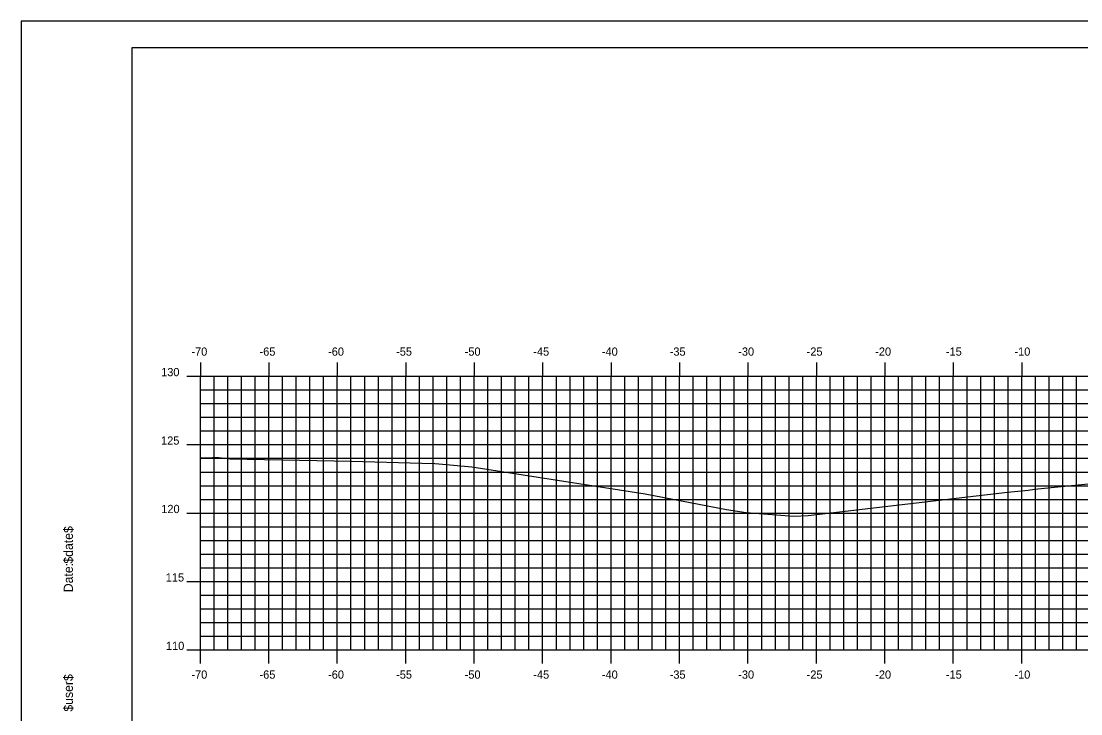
# Model space of a CAD drawing. Extents: x 852182 to 852354, y 365624 to 365734.
# Drawn here: x 852181.9 to 852259.3, y 365683.4 to 365734 of the extents above; entities that cross this region are included whole.
import ezdxf

# ---------------------------------------------------------------- set-up
doc = ezdxf.new("R2010")
doc.units = 0
for name, color, linetype in [('BORDER', 7, 'Continuous'), ('H_V ANNOTATION', 7, 'Continuous'), ('M_Roadway_Centerline', 7, 'Continuous'), ('MAJOR', 7, 'Continuous'), ('MINOR', 7, 'Continuous'), ('PLOT BOUNDARY', 7, 'Continuous'), ('S_Roadway_Centerline', 7, 'Continuous')]:
    doc.layers.add(name, color=color, linetype=linetype)

msp = doc.modelspace()

# ---------------------------------------------------------------- linework, layer by layer
at = {"layer": 'BORDER'}
msp.add_lwpolyline([(852190.035, 365627.027), (852350.035, 365627.027), (852350.035, 365732.027), (852190.035, 365732.027)], close=True, dxfattribs=at)
at = {"layer": 'MAJOR'}
for p, q in [((852195.035, 365709.029), (852195.035, 365708.027)), ((852200.035, 365709.029), (852200.035, 365708.027)), ((852205.035, 365709.029), (852205.035, 365708.027)), ((852210.035, 365709.029), (852210.035, 365708.027)), ((852215.035, 365709.029), (852215.035, 365708.027)), ((852220.035, 365709.029), (852220.035, 365708.027)), ((852225.035, 365709.029), (852225.035, 365708.027)), ((852230.035, 365709.029), (852230.035, 365708.027)), ((852235.035, 365709.029), (852235.035, 365708.027)), ((852240.035, 365709.029), (852240.035, 365708.027)), ((852245.035, 365709.029), (852245.035, 365708.027)), ((852250.035, 365709.029), (852250.035, 365708.027)), ((852255.035, 365709.029), (852255.035, 365708.027)), ((852194.033, 365708.027), (852195.035, 365708.027)), ((852195.035, 365708.027), (852335.035, 365708.027)), ((852195.035, 365688.027), (852195.035, 365708.027)), ((852195.035, 365688.027), (852195.035, 365708.027)), ((852195.035, 365708.027), (852335.035, 365708.027)), ((852200.035, 365688.027), (852200.035, 365708.027)), ((852205.035, 365688.027), (852205.035, 365708.027)), ((852210.035, 365688.027), (852210.035, 365708.027)), ((852215.035, 365688.027), (852215.035, 365708.027)), ((852220.035, 365688.027), (852220.035, 365708.027)), ((852225.035, 365688.027), (852225.035, 365708.027)), ((852230.035, 365688.027), (852230.035, 365708.027)), ((852235.035, 365688.027), (852235.035, 365708.027)), ((852240.035, 365688.027), (852240.035, 365708.027)), ((852245.035, 365688.027), (852245.035, 365708.027)), ((852250.035, 365688.027), (852250.035, 365708.027)), ((852255.035, 365688.027), (852255.035, 365708.027)), ((852194.033, 365703.027), (852195.035, 365703.027)), ((852195.035, 365703.027), (852335.035, 365703.027)), ((852194.033, 365698.027), (852195.035, 365698.027)), ((852195.035, 365698.027), (852335.035, 365698.027)), ((852194.033, 365693.027), (852195.035, 365693.027)), ((852195.035, 365693.027), (852335.035, 365693.027)), ((852194.033, 365688.027), (852195.035, 365688.027)), ((852195.035, 365688.027), (852335.035, 365688.027)), ((852195.035, 365688.027), (852335.035, 365688.027)), ((852195.035, 365687.025), (852195.035, 365688.027)), ((852200.035, 365687.025), (852200.035, 365688.027)), ((852205.035, 365687.025), (852205.035, 365688.027)), ((852210.035, 365687.025), (852210.035, 365688.027)), ((852215.035, 365687.025), (852215.035, 365688.027)), ((852220.035, 365687.025), (852220.035, 365688.027)), ((852225.035, 365687.025), (852225.035, 365688.027)), ((852230.035, 365687.025), (852230.035, 365688.027)), ((852235.035, 365687.025), (852235.035, 365688.027)), ((852240.035, 365687.025), (852240.035, 365688.027)), ((852245.035, 365687.025), (852245.035, 365688.027)), ((852250.035, 365687.025), (852250.035, 365688.027)), ((852255.035, 365687.025), (852255.035, 365688.027))]:
    msp.add_line(p, q, dxfattribs=at)
at = {"layer": 'MINOR'}
for p, q in [((852196.035, 365688.027), (852196.035, 365708.027)), ((852197.035, 365688.027), (852197.035, 365708.027)), ((852198.035, 365688.027), (852198.035, 365708.027)), ((852199.035, 365688.027), (852199.035, 365708.027)), ((852201.035, 365688.027), (852201.035, 365708.027)), ((852202.035, 365688.027), (852202.035, 365708.027)), ((852203.035, 365688.027), (852203.035, 365708.027)), ((852204.035, 365688.027), (852204.035, 365708.027)), ((852206.035, 365688.027), (852206.035, 365708.027)), ((852207.035, 365688.027), (852207.035, 365708.027)), ((852208.035, 365688.027), (852208.035, 365708.027)), ((852209.035, 365688.027), (852209.035, 365708.027)), ((852211.035, 365688.027), (852211.035, 365708.027)), ((852212.035, 365688.027), (852212.035, 365708.027)), ((852213.035, 365688.027), (852213.035, 365708.027)), ((852214.035, 365688.027), (852214.035, 365708.027)), ((852216.035, 365688.027), (852216.035, 365708.027)), ((852217.035, 365688.027), (852217.035, 365708.027)), ((852218.035, 365688.027), (852218.035, 365708.027)), ((852219.035, 365688.027), (852219.035, 365708.027)), ((852221.035, 365688.027), (852221.035, 365708.027)), ((852222.035, 365688.027), (852222.035, 365708.027)), ((852223.035, 365688.027), (852223.035, 365708.027)), ((852224.035, 365688.027), (852224.035, 365708.027)), ((852226.035, 365688.027), (852226.035, 365708.027)), ((852227.035, 365688.027), (852227.035, 365708.027)), ((852228.035, 365688.027), (852228.035, 365708.027)), ((852229.035, 365688.027), (852229.035, 365708.027)), ((852231.035, 365688.027), (852231.035, 365708.027)), ((852232.035, 365688.027), (852232.035, 365708.027)), ((852233.035, 365688.027), (852233.035, 365708.027)), ((852234.035, 365688.027), (852234.035, 365708.027)), ((852236.035, 365688.027), (852236.035, 365708.027)), ((852237.035, 365688.027), (852237.035, 365708.027)), ((852238.035, 365688.027), (852238.035, 365708.027)), ((852239.035, 365688.027), (852239.035, 365708.027)), ((852241.035, 365688.027), (852241.035, 365708.027)), ((852242.035, 365688.027), (852242.035, 365708.027)), ((852243.035, 365688.027), (852243.035, 365708.027)), ((852244.035, 365688.027), (852244.035, 365708.027)), ((852246.035, 365688.027), (852246.035, 365708.027)), ((852247.035, 365688.027), (852247.035, 365708.027)), ((852248.035, 365688.027), (852248.035, 365708.027)), ((852249.035, 365688.027), (852249.035, 365708.027)), ((852251.035, 365688.027), (852251.035, 365708.027)), ((852252.035, 365688.027), (852252.035, 365708.027)), ((852253.035, 365688.027), (852253.035, 365708.027)), ((852254.035, 365688.027), (852254.035, 365708.027)), ((852256.035, 365688.027), (852256.035, 365708.027)), ((852257.035, 365688.027), (852257.035, 365708.027)), ((852258.035, 365688.027), (852258.035, 365708.027)), ((852259.035, 365688.027), (852259.035, 365708.027)), ((852195.035, 365707.027), (852335.035, 365707.027)), ((852195.035, 365707.027), (852196.037, 365707.027)), ((852195.035, 365706.027), (852335.035, 365706.027)), ((852195.035, 365706.027), (852196.037, 365706.027)), ((852195.035, 365705.027), (852335.035, 365705.027)), ((852195.035, 365705.027), (852196.037, 365705.027)), ((852195.035, 365704.027), (852335.035, 365704.027)), ((852195.035, 365704.027), (852196.037, 365704.027)), ((852195.035, 365702.027), (852335.035, 365702.027)), ((852195.035, 365702.027), (852196.037, 365702.027)), ((852195.035, 365701.027), (852335.035, 365701.027)), ((852195.035, 365701.027), (852196.037, 365701.027)), ((852195.035, 365700.027), (852335.035, 365700.027)), ((852195.035, 365700.027), (852196.037, 365700.027)), ((852195.035, 365699.027), (852335.035, 365699.027)), ((852195.035, 365699.027), (852196.037, 365699.027)), ((852195.035, 365697.027), (852335.035, 365697.027)), ((852195.035, 365697.027), (852196.037, 365697.027)), ((852195.035, 365696.027), (852335.035, 365696.027)), ((852195.035, 365696.027), (852196.037, 365696.027)), ((852195.035, 365695.027), (852335.035, 365695.027)), ((852195.035, 365695.027), (852196.037, 365695.027)), ((852195.035, 365694.027), (852335.035, 365694.027)), ((852195.035, 365694.027), (852196.037, 365694.027)), ((852195.035, 365692.027), (852335.035, 365692.027)), ((852195.035, 365692.027), (852196.037, 365692.027)), ((852195.035, 365691.027), (852335.035, 365691.027)), ((852195.035, 365691.027), (852196.037, 365691.027)), ((852195.035, 365690.027), (852335.035, 365690.027)), ((852195.035, 365690.027), (852196.037, 365690.027)), ((852195.035, 365689.027), (852335.035, 365689.027)), ((852195.035, 365689.027), (852196.037, 365689.027))]:
    msp.add_line(p, q, dxfattribs=at)
at = {"layer": 'PLOT BOUNDARY'}
msp.add_lwpolyline([(852181.942, 365623.968), (852351.942, 365623.968), (852351.942, 365733.968), (852181.942, 365733.968)], close=True, dxfattribs=at)
at = {"layer": 'S_Roadway_Centerline'}
msp.add_lwpolyline([(852195.035, 365702.054), (852195.921, 365702.078), (852196.326, 365702.09), (852196.377, 365702.088), (852197.182, 365701.989), (852206.073, 365701.822), (852211.215, 365701.684), (852212.164, 365701.651), (852212.444, 365701.619), (852214.859, 365701.403), (852227.528, 365699.44), (852233.454, 365698.291), (852234.904, 365698.071), (852238.39, 365697.795), (852239.432, 365697.858), (852253.991, 365699.548), (852255.506, 365699.708), (852255.96, 365699.769), (852256.687, 365699.838), (852261.621, 365700.327)], dxfattribs=at)

# ---------------------------------------------------------------- texts
at = {"layer": 'BORDER'}
for s, p in [('$date$', (852185.72, 365694.332)), ('Date:', (852185.72, 365692.244)), ('$user$', (852185.72, 365683.518))]:
    msp.add_text(s, height=0.6696, rotation=90, dxfattribs=at).set_placement(p)
at = {"layer": 'H_V ANNOTATION'}
for s, p in [('-70', (852194.377, 365709.527)), ('-65', (852199.353, 365709.527)), ('-60', (852204.361, 365709.527)), ('-55', (852209.331, 365709.527)), ('-50', (852214.339, 365709.527)), ('-45', (852219.353, 365709.527)), ('-40', (852224.361, 365709.527)), ('-35', (852229.315, 365709.527)), ('-30', (852234.323, 365709.527)), ('-25', (852239.321, 365709.527)), ('-20', (852244.329, 365709.527)), ('-15', (852249.492, 365709.527)), ('-10', (852254.5, 365709.527)), ('130', (852192.165, 365708.027)), ('125', (852192.16, 365703.027)), ('120', (852192.176, 365698.027)), ('115', (852192.503, 365693.027)), ('110', (852192.519, 365688.027)), ('-70', (852194.377, 365685.927)), ('-65', (852199.353, 365685.927)), ('-60', (852204.361, 365685.927)), ('-55', (852209.331, 365685.927)), ('-50', (852214.339, 365685.927)), ('-45', (852219.353, 365685.927)), ('-40', (852224.361, 365685.927)), ('-35', (852229.315, 365685.927)), ('-30', (852234.323, 365685.927)), ('-25', (852239.321, 365685.927)), ('-20', (852244.329, 365685.927)), ('-15', (852249.492, 365685.927)), ('-10', (852254.5, 365685.927))]:
    msp.add_text(s, height=0.6, dxfattribs=at).set_placement(p)
at = {"layer": 'M_Roadway_Centerline'}
for s, p in [('C', (852196.32, 365702.09)), ('L', (852196.326, 365702.083))]:
    msp.add_text(s, height=0.0146, dxfattribs=at).set_placement(p)
at = {"layer": 'MAJOR'}
msp.add_text('-', height=0.006, dxfattribs=at).set_placement((852195.031, 365688.027))

doc.saveas('drawing.dxf')
